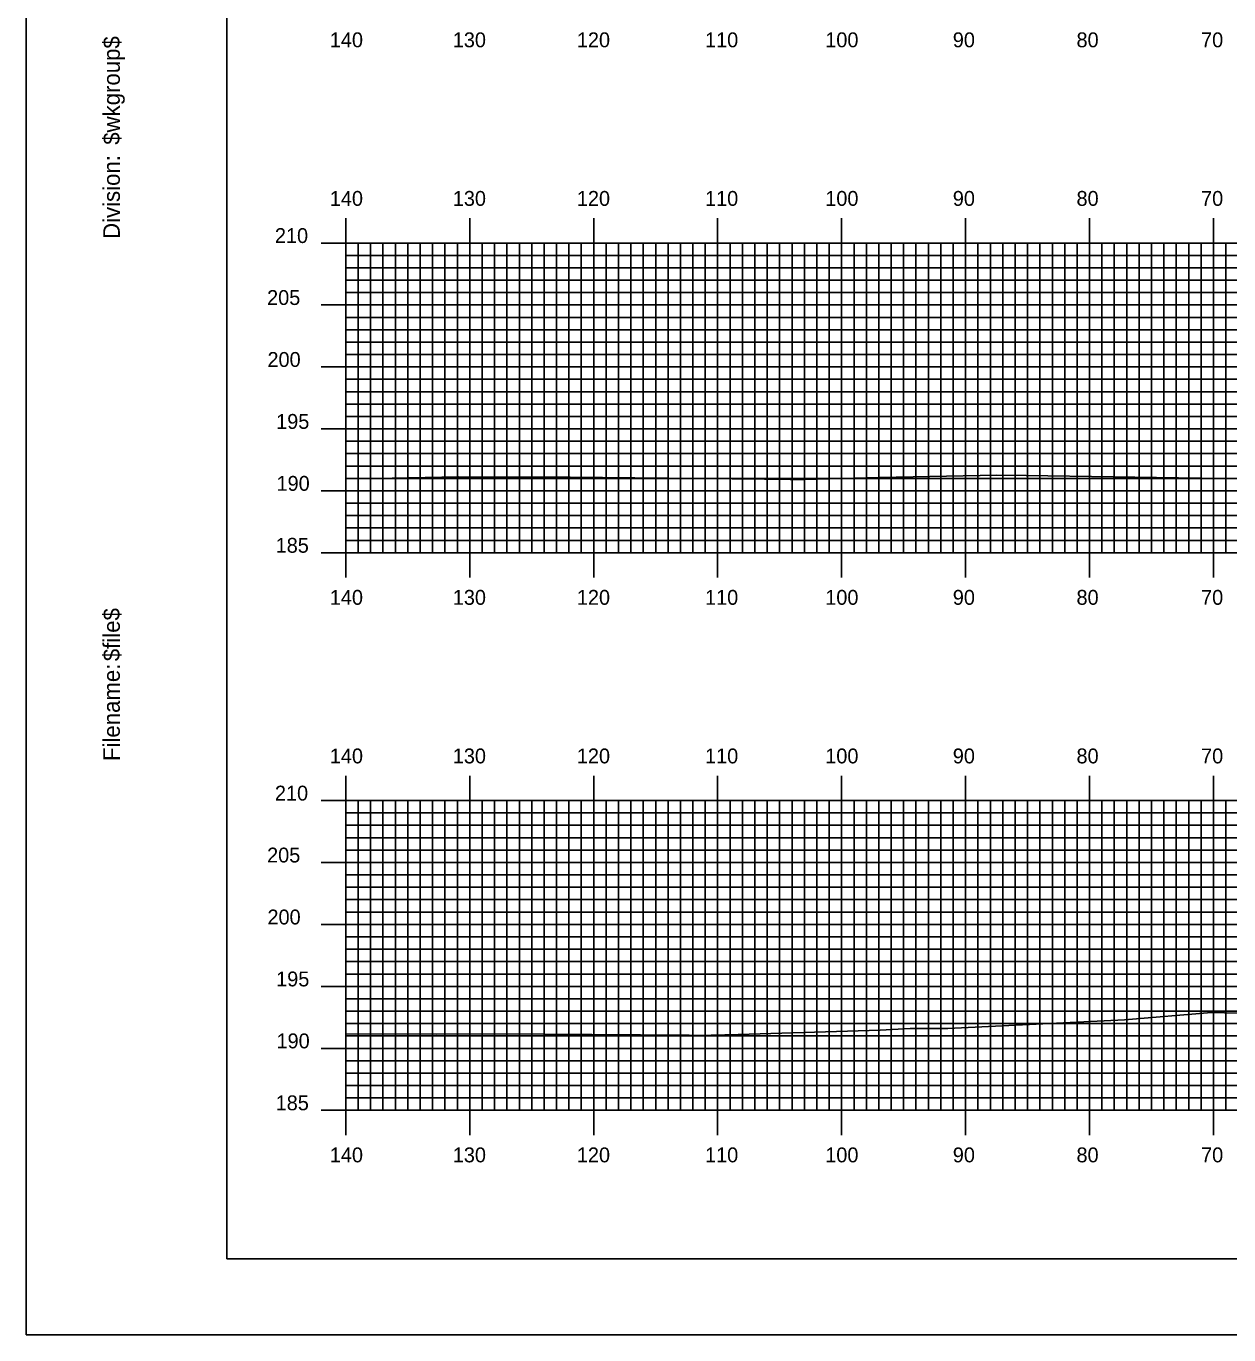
# Model space of a CAD drawing. Extents: x 1814915 to 1815259, y 442591 to 442811.
# Drawn here: x 1814915.2 to 1815012.3, y 442590.5 to 442696.2 of the extents above; entities that cross this region are included whole.
import ezdxf

# ---------------------------------------------------------------- set-up
doc = ezdxf.new("R2010")
doc.units = 0
for name, color, linetype in [('BORDER', 7, 'Continuous'), ('H_V ANNOTATION', 7, 'Continuous'), ('MAJOR', 7, 'Continuous'), ('MINOR', 7, 'Continuous'), ('PLOT BOUNDARY', 7, 'Continuous'), ('S_Roadway_Centerline', 7, 'Continuous')]:
    doc.layers.add(name, color=color, linetype=linetype)

msp = doc.modelspace()

# ---------------------------------------------------------------- linework, layer by layer
at = {"layer": 'BORDER'}
msp.add_lwpolyline([(1814931.42, 442596.67), (1815251.42, 442596.67), (1815251.42, 442806.67), (1814931.42, 442806.67)], close=True, dxfattribs=at)
at = {"layer": 'MAJOR'}
for p, q in [((1814941.02, 442680.67), (1814941.02, 442678.67)), ((1814951.02, 442680.67), (1814951.02, 442678.67)), ((1814961.02, 442680.67), (1814961.02, 442678.67)), ((1814971.02, 442680.67), (1814971.02, 442678.67)), ((1814981.02, 442680.67), (1814981.02, 442678.67)), ((1814991.02, 442680.67), (1814991.02, 442678.67)), ((1815001.02, 442680.67), (1815001.02, 442678.67)), ((1815011.02, 442680.67), (1815011.02, 442678.67)), ((1814939.02, 442678.67), (1814941.02, 442678.67)), ((1814941.02, 442678.67), (1815221.02, 442678.67)), ((1814941.02, 442653.67), (1814941.02, 442678.67)), ((1814941.02, 442653.67), (1814941.02, 442678.67)), ((1814941.02, 442678.67), (1815221.02, 442678.67)), ((1814951.02, 442653.67), (1814951.02, 442678.67)), ((1814961.02, 442653.67), (1814961.02, 442678.67)), ((1814971.02, 442653.67), (1814971.02, 442678.67)), ((1814981.02, 442653.67), (1814981.02, 442678.67)), ((1814991.02, 442653.67), (1814991.02, 442678.67)), ((1815001.02, 442653.67), (1815001.02, 442678.67)), ((1815011.02, 442653.67), (1815011.02, 442678.67)), ((1814939.02, 442673.67), (1814941.02, 442673.67)), ((1814941.02, 442673.67), (1815221.02, 442673.67)), ((1814939.02, 442668.67), (1814941.02, 442668.67)), ((1814941.02, 442668.67), (1815221.02, 442668.67)), ((1814939.02, 442663.67), (1814941.02, 442663.67)), ((1814941.02, 442663.67), (1815221.02, 442663.67)), ((1814939.02, 442658.67), (1814941.02, 442658.67)), ((1814941.02, 442658.67), (1815221.02, 442658.67)), ((1814939.02, 442653.67), (1814941.02, 442653.67)), ((1814941.02, 442653.67), (1815221.02, 442653.67)), ((1814941.02, 442653.67), (1815221.02, 442653.67)), ((1814941.02, 442651.66), (1814941.02, 442653.67)), ((1814951.02, 442651.66), (1814951.02, 442653.67)), ((1814961.02, 442651.66), (1814961.02, 442653.67)), ((1814971.02, 442651.66), (1814971.02, 442653.67)), ((1814981.02, 442651.66), (1814981.02, 442653.67)), ((1814991.02, 442651.66), (1814991.02, 442653.67)), ((1815001.02, 442651.66), (1815001.02, 442653.67)), ((1815011.02, 442651.66), (1815011.02, 442653.67)), ((1814941.02, 442635.67), (1814941.02, 442633.67)), ((1814951.02, 442635.67), (1814951.02, 442633.67)), ((1814961.02, 442635.67), (1814961.02, 442633.67)), ((1814971.02, 442635.67), (1814971.02, 442633.67)), ((1814981.02, 442635.67), (1814981.02, 442633.67)), ((1814991.02, 442635.67), (1814991.02, 442633.67)), ((1815001.02, 442635.67), (1815001.02, 442633.67)), ((1815011.02, 442635.67), (1815011.02, 442633.67)), ((1814939.02, 442633.67), (1814941.02, 442633.67)), ((1814941.02, 442633.67), (1815221.02, 442633.67)), ((1814941.02, 442608.67), (1814941.02, 442633.67)), ((1814941.02, 442608.67), (1814941.02, 442633.67)), ((1814941.02, 442633.67), (1815221.02, 442633.67)), ((1814951.02, 442608.67), (1814951.02, 442633.67)), ((1814961.02, 442608.67), (1814961.02, 442633.67)), ((1814971.02, 442608.67), (1814971.02, 442633.67)), ((1814981.02, 442608.67), (1814981.02, 442633.67)), ((1814991.02, 442608.67), (1814991.02, 442633.67)), ((1815001.02, 442608.67), (1815001.02, 442633.67)), ((1815011.02, 442608.67), (1815011.02, 442633.67)), ((1814939.02, 442628.67), (1814941.02, 442628.67)), ((1814941.02, 442628.67), (1815221.02, 442628.67)), ((1814939.02, 442623.67), (1814941.02, 442623.67)), ((1814941.02, 442623.67), (1815221.02, 442623.67)), ((1814939.02, 442618.67), (1814941.02, 442618.67)), ((1814941.02, 442618.67), (1815221.02, 442618.67)), ((1814939.02, 442613.67), (1814941.02, 442613.67)), ((1814941.02, 442613.67), (1815221.02, 442613.67)), ((1814939.02, 442608.67), (1814941.02, 442608.67)), ((1814941.02, 442608.67), (1815221.02, 442608.67)), ((1814941.02, 442608.67), (1815221.02, 442608.67)), ((1814941.02, 442606.66), (1814941.02, 442608.67)), ((1814951.02, 442606.66), (1814951.02, 442608.67)), ((1814961.02, 442606.66), (1814961.02, 442608.67)), ((1814971.02, 442606.66), (1814971.02, 442608.67)), ((1814981.02, 442606.66), (1814981.02, 442608.67)), ((1814991.02, 442606.66), (1814991.02, 442608.67)), ((1815001.02, 442606.66), (1815001.02, 442608.67)), ((1815011.02, 442606.66), (1815011.02, 442608.67))]:
    msp.add_line(p, q, dxfattribs=at)
at = {"layer": 'MINOR'}
for p, q in [((1814942.02, 442653.67), (1814942.02, 442678.67)), ((1814943.02, 442653.67), (1814943.02, 442678.67)), ((1814944.02, 442653.67), (1814944.02, 442678.67)), ((1814945.02, 442653.67), (1814945.02, 442678.67)), ((1814946.02, 442653.67), (1814946.02, 442678.67)), ((1814947.02, 442653.67), (1814947.02, 442678.67)), ((1814948.02, 442653.67), (1814948.02, 442678.67)), ((1814949.02, 442653.67), (1814949.02, 442678.67)), ((1814950.02, 442653.67), (1814950.02, 442678.67)), ((1814952.02, 442653.67), (1814952.02, 442678.67)), ((1814953.02, 442653.67), (1814953.02, 442678.67)), ((1814954.02, 442653.67), (1814954.02, 442678.67)), ((1814955.02, 442653.67), (1814955.02, 442678.67)), ((1814956.02, 442653.67), (1814956.02, 442678.67)), ((1814957.02, 442653.67), (1814957.02, 442678.67)), ((1814958.02, 442653.67), (1814958.02, 442678.67)), ((1814959.02, 442653.67), (1814959.02, 442678.67)), ((1814960.02, 442653.67), (1814960.02, 442678.67)), ((1814962.02, 442653.67), (1814962.02, 442678.67)), ((1814963.02, 442653.67), (1814963.02, 442678.67)), ((1814964.02, 442653.67), (1814964.02, 442678.67)), ((1814965.02, 442653.67), (1814965.02, 442678.67)), ((1814966.02, 442653.67), (1814966.02, 442678.67)), ((1814967.02, 442653.67), (1814967.02, 442678.67)), ((1814968.02, 442653.67), (1814968.02, 442678.67)), ((1814969.02, 442653.67), (1814969.02, 442678.67)), ((1814970.02, 442653.67), (1814970.02, 442678.67)), ((1814972.02, 442653.67), (1814972.02, 442678.67)), ((1814973.02, 442653.67), (1814973.02, 442678.67)), ((1814974.02, 442653.67), (1814974.02, 442678.67)), ((1814975.02, 442653.67), (1814975.02, 442678.67)), ((1814976.02, 442653.67), (1814976.02, 442678.67)), ((1814977.02, 442653.67), (1814977.02, 442678.67)), ((1814978.02, 442653.67), (1814978.02, 442678.67)), ((1814979.02, 442653.67), (1814979.02, 442678.67)), ((1814980.02, 442653.67), (1814980.02, 442678.67)), ((1814982.02, 442653.67), (1814982.02, 442678.67)), ((1814983.02, 442653.67), (1814983.02, 442678.67)), ((1814984.02, 442653.67), (1814984.02, 442678.67)), ((1814985.02, 442653.67), (1814985.02, 442678.67)), ((1814986.02, 442653.67), (1814986.02, 442678.67)), ((1814987.02, 442653.67), (1814987.02, 442678.67)), ((1814988.02, 442653.67), (1814988.02, 442678.67)), ((1814989.02, 442653.67), (1814989.02, 442678.67)), ((1814990.02, 442653.67), (1814990.02, 442678.67)), ((1814992.02, 442653.67), (1814992.02, 442678.67)), ((1814993.02, 442653.67), (1814993.02, 442678.67)), ((1814994.02, 442653.67), (1814994.02, 442678.67)), ((1814995.02, 442653.67), (1814995.02, 442678.67)), ((1814996.02, 442653.67), (1814996.02, 442678.67)), ((1814997.02, 442653.67), (1814997.02, 442678.67)), ((1814998.02, 442653.67), (1814998.02, 442678.67)), ((1814999.02, 442653.67), (1814999.02, 442678.67)), ((1815000.02, 442653.67), (1815000.02, 442678.67)), ((1815002.02, 442653.67), (1815002.02, 442678.67)), ((1815003.02, 442653.67), (1815003.02, 442678.67)), ((1815004.02, 442653.67), (1815004.02, 442678.67)), ((1815005.02, 442653.67), (1815005.02, 442678.67)), ((1815006.02, 442653.67), (1815006.02, 442678.67)), ((1815007.02, 442653.67), (1815007.02, 442678.67)), ((1815008.02, 442653.67), (1815008.02, 442678.67)), ((1815009.02, 442653.67), (1815009.02, 442678.67)), ((1815010.02, 442653.67), (1815010.02, 442678.67)), ((1815012.02, 442653.67), (1815012.02, 442678.67)), ((1814941.02, 442677.67), (1815221.02, 442677.67)), ((1814941.02, 442677.67), (1814943.02, 442677.67)), ((1814941.02, 442676.67), (1815221.02, 442676.67)), ((1814941.02, 442676.67), (1814943.02, 442676.67)), ((1814941.02, 442675.67), (1815221.02, 442675.67)), ((1814941.02, 442675.67), (1814943.02, 442675.67)), ((1814941.02, 442674.67), (1815221.02, 442674.67)), ((1814941.02, 442674.67), (1814943.02, 442674.67)), ((1814941.02, 442672.67), (1815221.02, 442672.67)), ((1814941.02, 442672.67), (1814943.02, 442672.67)), ((1814941.02, 442671.67), (1815221.02, 442671.67)), ((1814941.02, 442671.67), (1814943.02, 442671.67)), ((1814941.02, 442670.67), (1815221.02, 442670.67)), ((1814941.02, 442670.67), (1814943.02, 442670.67)), ((1814941.02, 442669.67), (1815221.02, 442669.67)), ((1814941.02, 442669.67), (1814943.02, 442669.67)), ((1814941.02, 442667.67), (1815221.02, 442667.67)), ((1814941.02, 442667.67), (1814943.02, 442667.67)), ((1814941.02, 442666.67), (1815221.02, 442666.67)), ((1814941.02, 442666.67), (1814943.02, 442666.67)), ((1814941.02, 442665.67), (1815221.02, 442665.67)), ((1814941.02, 442665.67), (1814943.02, 442665.67)), ((1814941.02, 442664.67), (1815221.02, 442664.67)), ((1814941.02, 442664.67), (1814943.02, 442664.67)), ((1814941.02, 442662.67), (1815221.02, 442662.67)), ((1814941.02, 442662.67), (1814943.02, 442662.67)), ((1814941.02, 442661.67), (1815221.02, 442661.67)), ((1814941.02, 442661.67), (1814943.02, 442661.67)), ((1814941.02, 442660.67), (1815221.02, 442660.67)), ((1814941.02, 442660.67), (1814943.02, 442660.67)), ((1814941.02, 442659.67), (1815221.02, 442659.67)), ((1814941.02, 442659.67), (1814943.02, 442659.67)), ((1814941.02, 442657.67), (1815221.02, 442657.67)), ((1814941.02, 442657.67), (1814943.02, 442657.67)), ((1814941.02, 442656.67), (1815221.02, 442656.67)), ((1814941.02, 442656.67), (1814943.02, 442656.67)), ((1814941.02, 442655.67), (1815221.02, 442655.67)), ((1814941.02, 442655.67), (1814943.02, 442655.67)), ((1814941.02, 442654.67), (1815221.02, 442654.67)), ((1814941.02, 442654.67), (1814943.02, 442654.67)), ((1814942.02, 442608.67), (1814942.02, 442633.67)), ((1814943.02, 442608.67), (1814943.02, 442633.67)), ((1814944.02, 442608.67), (1814944.02, 442633.67)), ((1814945.02, 442608.67), (1814945.02, 442633.67)), ((1814946.02, 442608.67), (1814946.02, 442633.67)), ((1814947.02, 442608.67), (1814947.02, 442633.67)), ((1814948.02, 442608.67), (1814948.02, 442633.67)), ((1814949.02, 442608.67), (1814949.02, 442633.67)), ((1814950.02, 442608.67), (1814950.02, 442633.67)), ((1814952.02, 442608.67), (1814952.02, 442633.67)), ((1814953.02, 442608.67), (1814953.02, 442633.67)), ((1814954.02, 442608.67), (1814954.02, 442633.67)), ((1814955.02, 442608.67), (1814955.02, 442633.67)), ((1814956.02, 442608.67), (1814956.02, 442633.67)), ((1814957.02, 442608.67), (1814957.02, 442633.67)), ((1814958.02, 442608.67), (1814958.02, 442633.67)), ((1814959.02, 442608.67), (1814959.02, 442633.67)), ((1814960.02, 442608.67), (1814960.02, 442633.67)), ((1814962.02, 442608.67), (1814962.02, 442633.67)), ((1814963.02, 442608.67), (1814963.02, 442633.67)), ((1814964.02, 442608.67), (1814964.02, 442633.67)), ((1814965.02, 442608.67), (1814965.02, 442633.67)), ((1814966.02, 442608.67), (1814966.02, 442633.67)), ((1814967.02, 442608.67), (1814967.02, 442633.67)), ((1814968.02, 442608.67), (1814968.02, 442633.67)), ((1814969.02, 442608.67), (1814969.02, 442633.67)), ((1814970.02, 442608.67), (1814970.02, 442633.67)), ((1814972.02, 442608.67), (1814972.02, 442633.67)), ((1814973.02, 442608.67), (1814973.02, 442633.67)), ((1814974.02, 442608.67), (1814974.02, 442633.67)), ((1814975.02, 442608.67), (1814975.02, 442633.67)), ((1814976.02, 442608.67), (1814976.02, 442633.67)), ((1814977.02, 442608.67), (1814977.02, 442633.67)), ((1814978.02, 442608.67), (1814978.02, 442633.67)), ((1814979.02, 442608.67), (1814979.02, 442633.67)), ((1814980.02, 442608.67), (1814980.02, 442633.67)), ((1814982.02, 442608.67), (1814982.02, 442633.67)), ((1814983.02, 442608.67), (1814983.02, 442633.67)), ((1814984.02, 442608.67), (1814984.02, 442633.67)), ((1814985.02, 442608.67), (1814985.02, 442633.67)), ((1814986.02, 442608.67), (1814986.02, 442633.67)), ((1814987.02, 442608.67), (1814987.02, 442633.67)), ((1814988.02, 442608.67), (1814988.02, 442633.67)), ((1814989.02, 442608.67), (1814989.02, 442633.67)), ((1814990.02, 442608.67), (1814990.02, 442633.67)), ((1814992.02, 442608.67), (1814992.02, 442633.67)), ((1814993.02, 442608.67), (1814993.02, 442633.67)), ((1814994.02, 442608.67), (1814994.02, 442633.67)), ((1814995.02, 442608.67), (1814995.02, 442633.67)), ((1814996.02, 442608.67), (1814996.02, 442633.67)), ((1814997.02, 442608.67), (1814997.02, 442633.67)), ((1814998.02, 442608.67), (1814998.02, 442633.67)), ((1814999.02, 442608.67), (1814999.02, 442633.67)), ((1815000.02, 442608.67), (1815000.02, 442633.67)), ((1815002.02, 442608.67), (1815002.02, 442633.67)), ((1815003.02, 442608.67), (1815003.02, 442633.67)), ((1815004.02, 442608.67), (1815004.02, 442633.67)), ((1815005.02, 442608.67), (1815005.02, 442633.67)), ((1815006.02, 442608.67), (1815006.02, 442633.67)), ((1815007.02, 442608.67), (1815007.02, 442633.67)), ((1815008.02, 442608.67), (1815008.02, 442633.67)), ((1815009.02, 442608.67), (1815009.02, 442633.67)), ((1815010.02, 442608.67), (1815010.02, 442633.67)), ((1815012.02, 442608.67), (1815012.02, 442633.67)), ((1814941.02, 442632.67), (1815221.02, 442632.67)), ((1814941.02, 442632.67), (1814943.02, 442632.67)), ((1814941.02, 442631.67), (1815221.02, 442631.67)), ((1814941.02, 442631.67), (1814943.02, 442631.67)), ((1814941.02, 442630.67), (1815221.02, 442630.67)), ((1814941.02, 442630.67), (1814943.02, 442630.67)), ((1814941.02, 442629.67), (1815221.02, 442629.67)), ((1814941.02, 442629.67), (1814943.02, 442629.67)), ((1814941.02, 442627.67), (1815221.02, 442627.67)), ((1814941.02, 442627.67), (1814943.02, 442627.67)), ((1814941.02, 442626.67), (1815221.02, 442626.67)), ((1814941.02, 442626.67), (1814943.02, 442626.67)), ((1814941.02, 442625.67), (1815221.02, 442625.67)), ((1814941.02, 442625.67), (1814943.02, 442625.67)), ((1814941.02, 442624.67), (1815221.02, 442624.67)), ((1814941.02, 442624.67), (1814943.02, 442624.67)), ((1814941.02, 442622.67), (1815221.02, 442622.67)), ((1814941.02, 442622.67), (1814943.02, 442622.67)), ((1814941.02, 442621.67), (1815221.02, 442621.67)), ((1814941.02, 442621.67), (1814943.02, 442621.67)), ((1814941.02, 442620.67), (1815221.02, 442620.67)), ((1814941.02, 442620.67), (1814943.02, 442620.67)), ((1814941.02, 442619.67), (1815221.02, 442619.67)), ((1814941.02, 442619.67), (1814943.02, 442619.67)), ((1814941.02, 442617.67), (1815221.02, 442617.67)), ((1814941.02, 442617.67), (1814943.02, 442617.67)), ((1814941.02, 442616.67), (1815221.02, 442616.67)), ((1814941.02, 442616.67), (1814943.02, 442616.67)), ((1814941.02, 442615.67), (1815221.02, 442615.67)), ((1814941.02, 442615.67), (1814943.02, 442615.67)), ((1814941.02, 442614.67), (1815221.02, 442614.67)), ((1814941.02, 442614.67), (1814943.02, 442614.67)), ((1814941.02, 442612.67), (1815221.02, 442612.67)), ((1814941.02, 442612.67), (1814943.02, 442612.67)), ((1814941.02, 442611.67), (1815221.02, 442611.67)), ((1814941.02, 442611.67), (1814943.02, 442611.67)), ((1814941.02, 442610.67), (1815221.02, 442610.67)), ((1814941.02, 442610.67), (1814943.02, 442610.67)), ((1814941.02, 442609.67), (1815221.02, 442609.67)), ((1814941.02, 442609.67), (1814943.02, 442609.67))]:
    msp.add_line(p, q, dxfattribs=at)
at = {"layer": 'PLOT BOUNDARY'}
msp.add_lwpolyline([(1814915.23, 442590.55), (1815255.23, 442590.55), (1815255.23, 442810.55), (1814915.23, 442810.55)], close=True, dxfattribs=at)
at = {"layer": 'S_Roadway_Centerline'}
for points in [[(1814941.02, 442659.66), (1814943.41, 442659.66), (1814950.12, 442659.81), (1814959.11, 442659.76), (1814974.79, 442659.61), (1814976.87, 442659.57), (1814977.95, 442659.58), (1814984.07, 442659.74), (1814993.54, 442659.93), (1814995.91, 442659.9), (1815009.96, 442659.68), (1815019.41, 442659.59)], [(1814941.02, 442614.83), (1814948.35, 442614.82), (1814953.03, 442614.84), (1814968.72, 442614.72), (1814969.41, 442614.71), (1814972.67, 442614.8), (1814984.12, 442615.14), (1814986.56, 442615.26), (1814989.59, 442615.28), (1815003.85, 442615.98), (1815010.86, 442616.56), (1815020.3, 442616.33)]]:
    msp.add_lwpolyline(points, dxfattribs=at)

# ---------------------------------------------------------------- texts
at = {"layer": 'BORDER'}
for s, p in [('$wkgroup$', (1814922.79, 442686.6)), ('Division:', (1814922.79, 442679)), ('$file$', (1814922.79, 442644.92)), ('Filename:', (1814922.79, 442636.86))]:
    msp.add_text(s, height=1.339, rotation=90, dxfattribs=at).set_placement(p)
at = {"layer": 'H_V ANNOTATION'}
for s, p in [('140', (1814939.73, 442694.47)), ('130', (1814949.65, 442694.47)), ('120', (1814959.66, 442694.47)), ('110', (1814970, 442694.47)), ('100', (1814979.7, 442694.47)), ('90', (1814989.99, 442694.47)), ('80', (1814999.97, 442694.47)), ('70', (1815010.02, 442694.47)), ('140', (1814939.73, 442681.67)), ('130', (1814949.65, 442681.67)), ('120', (1814959.66, 442681.67)), ('110', (1814970, 442681.67)), ('100', (1814979.7, 442681.67)), ('90', (1814989.99, 442681.67)), ('80', (1814999.97, 442681.67)), ('70', (1815010.02, 442681.67)), ('210', (1814935.3, 442678.67)), ('205', (1814934.67, 442673.67)), ('200', (1814934.7, 442668.67)), ('195', (1814935.4, 442663.67)), ('190', (1814935.43, 442658.67)), ('185', (1814935.36, 442653.67)), ('140', (1814939.73, 442649.47)), ('130', (1814949.65, 442649.47)), ('120', (1814959.66, 442649.47)), ('110', (1814970, 442649.47)), ('100', (1814979.7, 442649.47)), ('90', (1814989.99, 442649.47)), ('80', (1814999.97, 442649.47)), ('70', (1815010.02, 442649.47)), ('140', (1814939.73, 442636.67)), ('130', (1814949.65, 442636.67)), ('120', (1814959.66, 442636.67)), ('110', (1814970, 442636.67)), ('100', (1814979.7, 442636.67)), ('90', (1814989.99, 442636.67)), ('80', (1814999.97, 442636.67)), ('70', (1815010.02, 442636.67)), ('210', (1814935.3, 442633.67)), ('205', (1814934.67, 442628.67)), ('200', (1814934.7, 442623.67)), ('195', (1814935.4, 442618.67)), ('190', (1814935.43, 442613.67)), ('185', (1814935.36, 442608.67)), ('140', (1814939.73, 442604.47)), ('130', (1814949.65, 442604.47)), ('120', (1814959.66, 442604.47)), ('110', (1814970, 442604.47)), ('100', (1814979.7, 442604.47)), ('90', (1814989.99, 442604.47)), ('80', (1814999.97, 442604.47)), ('70', (1815010.02, 442604.47))]:
    msp.add_text(s, height=1.2, dxfattribs=at).set_placement(p)
at = {"layer": 'MAJOR'}
for p in [(1814941.01, 442653.67), (1814941.01, 442608.67)]:
    msp.add_text('-', height=0.012, dxfattribs=at).set_placement(p)

doc.saveas('drawing.dxf')
